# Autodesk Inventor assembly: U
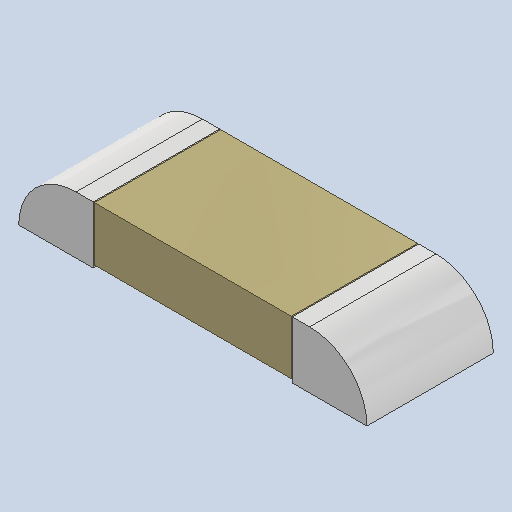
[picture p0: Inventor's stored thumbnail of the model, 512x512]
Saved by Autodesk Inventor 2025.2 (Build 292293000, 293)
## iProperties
Created: 2025-04
Part Number: U
Description: PART--DESC
Document SubType Name: Assembly
Designer: BennF
Author: BennF
Revision Number: NONE
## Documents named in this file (2)
- C:\Users\BennF\Nextcloud\Benutzer\CNC JarBeRi\existing parts\Electronics\RepRap A4988 Shied (USE WITHOUT ARDUINO)\reprap-a4988-1.snapshot.1\RepRap\RepRap\U.iam
- C:\Users\BennF\Nextcloud\Benutzer\CNC JarBeRi\existing parts\Electronics\RepRap A4988 Shied (USE WITHOUT ARDUINO)\reprap-a4988-1.snapshot.1\RepRap\RepRap\U2.ipt
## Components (1 placed, 1 different names)
1. U2
